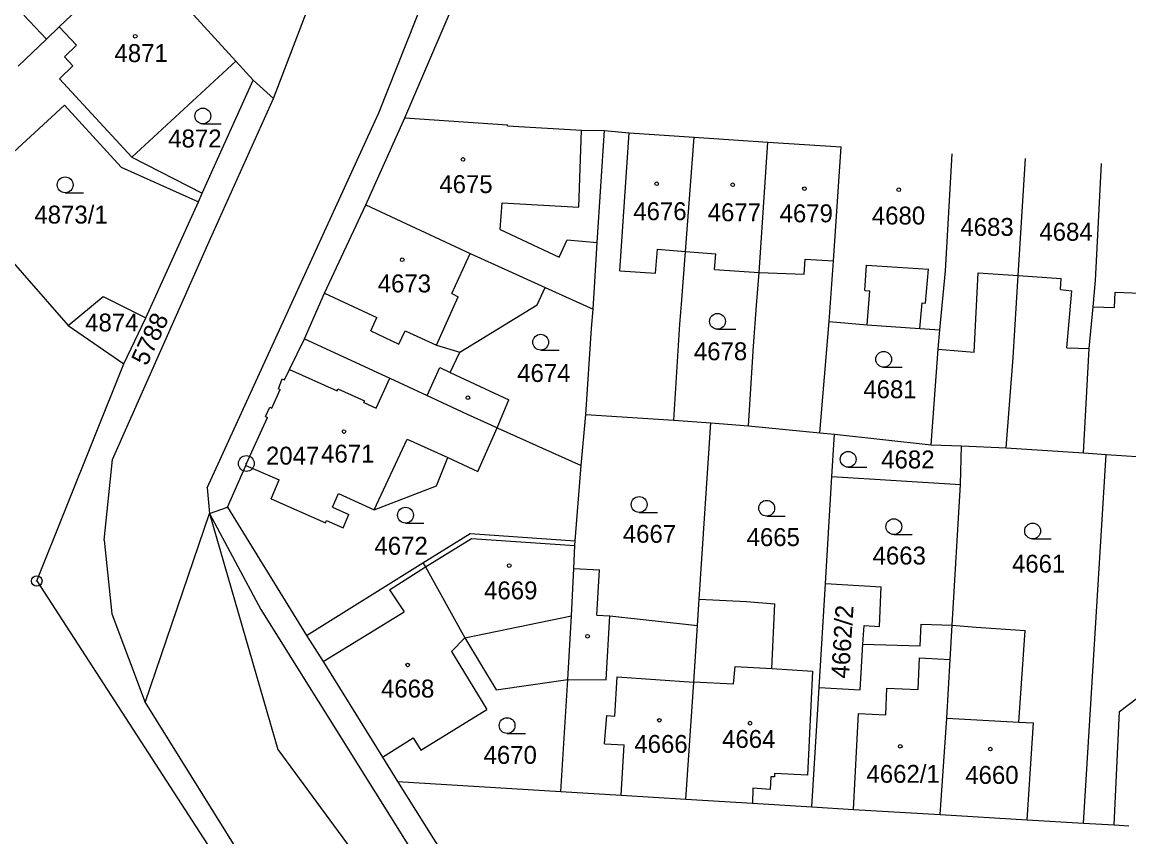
# Model space of a CAD drawing. Extents: x -735092 to -733385, y -1122435 to -1118992.
# Drawn here: x -734733.2 to -734628.2, y -1119440 to -1119362.8 of the extents above; entities that cross this region are included whole.
import ezdxf

# ---------------------------------------------------------------- set-up
doc = ezdxf.new("R2010")
doc.units = 0
for name, color, linetype in [('Vrstva 1', 7, 'Continuous'), ('Vrstva 17', 7, 'Continuous'), ('Vrstva 18', 7, 'Continuous'), ('Vrstva 19', 7, 'Continuous'), ('Vrstva 25', 7, 'Continuous'), ('Vrstva 4', 7, 'Continuous')]:
    doc.layers.add(name, color=color, linetype=linetype)

msp = doc.modelspace()

# ---------------------------------------------------------------- linework, layer by layer
at = {"layer": 'Vrstva 1'}
for points in [[(-734729.71, -1119363.21), (-734722.32, -1119356.18)], [(-734722.32, -1119356.18), (-734712.94, -1119366.45)], [(-734709.39, -1119370), (-734703.94, -1119355.73)], [(-734699.37, -1119371.37), (-734694.14, -1119358.12)], [(-734696.92, -1119371.82), (-734691.02, -1119358.02)], [(-734730.91, -1119364.36), (-734729.71, -1119363.21)], [(-734733.61, -1119366.92), (-734730.91, -1119364.36)], [(-734722.81, -1119375.57), (-734712.94, -1119366.45)], [(-734712.94, -1119366.45), (-734711.3, -1119368.27)], [(-734716.13, -1119378.97), (-734711.3, -1119368.27)], [(-734711.3, -1119368.27), (-734709.39, -1119370)], [(-734715.35, -1119383.29), (-734709.39, -1119370)], [(-734734.03, -1119375.09), (-734729.21, -1119370.63)], [(-734729.21, -1119370.63), (-734723.84, -1119376.52)], [(-734746.35, -1119371.53), (-734728.84, -1119391.54)], [(-734715.66, -1119406.92), (-734699.37, -1119371.37)], [(-734700.63, -1119380.07), (-734696.92, -1119371.82)], [(-734696.92, -1119371.82), (-734687.18, -1119372.48)], [(-734687.19, -1119372.6), (-734687.18, -1119372.48)], [(-734687.19, -1119372.6), (-734680.15, -1119372.99)], [(-734680.15, -1119372.99), (-734677.98, -1119373.03)], [(-734678.66, -1119383.67), (-734677.98, -1119373.03)], [(-734677.98, -1119373.03), (-734675.64, -1119373.26)], [(-734675.64, -1119373.26), (-734669.47, -1119373.67)], [(-734670.3, -1119384.52), (-734669.47, -1119373.67)], [(-734669.47, -1119373.67), (-734662.49, -1119374.13)], [(-734663.31, -1119386.51), (-734662.49, -1119374.13)], [(-734662.49, -1119374.13), (-734655.52, -1119374.58)], [(-734656.27, -1119385.39), (-734655.52, -1119374.58)], [(-734645.64, -1119386.33), (-734644.99, -1119375.26)], [(-734723.84, -1119376.52), (-734716.5, -1119379.79)], [(-734722.81, -1119375.57), (-734716.13, -1119378.97)], [(-734638.74, -1119386.8), (-734638.03, -1119375.7)], [(-734631.41, -1119387.27), (-734630.83, -1119376.15)], [(-734716.5, -1119379.79), (-734716.13, -1119378.97)], [(-734721.48, -1119390.8), (-734716.5, -1119379.79)], [(-734704.54, -1119388.46), (-734700.63, -1119380.07)], [(-734700.63, -1119380.07), (-734690.73, -1119384.71)], [(-734724.66, -1119404.24), (-734715.35, -1119383.29)], [(-734678.93, -1119387.92), (-734678.66, -1119383.67)], [(-734690.73, -1119384.71), (-734687.09, -1119386.36)], [(-734670.68, -1119389.51), (-734670.3, -1119384.52)], [(-734670.3, -1119384.52), (-734667.42, -1119384.72)], [(-734667.53, -1119386.21), (-734667.42, -1119384.72)], [(-734656.67, -1119391.16), (-734656.27, -1119385.39)], [(-734687.09, -1119386.36), (-734683.62, -1119387.93)], [(-734667.53, -1119386.21), (-734663.31, -1119386.51)], [(-734663.55, -1119389.63), (-734663.31, -1119386.51)], [(-734646.17, -1119391.94), (-734645.64, -1119386.33)], [(-734639.23, -1119394.58), (-734638.74, -1119386.8)], [(-734684.37, -1119389.57), (-734683.62, -1119387.93)], [(-734683.62, -1119387.93), (-734679.07, -1119389.99)], [(-734679.07, -1119389.99), (-734678.93, -1119387.92)], [(-734631.64, -1119389.75), (-734631.41, -1119387.27)], [(-734728.84, -1119391.54), (-734725.54, -1119388.79)], [(-734725.54, -1119388.79), (-734721.48, -1119390.8)], [(-734706.43, -1119392.79), (-734704.54, -1119388.46)], [(-734691.69, -1119394.05), (-734684.37, -1119389.57)], [(-734679.2, -1119391.82), (-734679.07, -1119389.99)], [(-734670.83, -1119391.4), (-734670.68, -1119389.51)], [(-734663.84, -1119393.5), (-734663.55, -1119389.63)], [(-734632, -1119393.73), (-734631.64, -1119389.75)], [(-734723.57, -1119395.17), (-734721.48, -1119390.8)], [(-734657.54, -1119401.71), (-734656.67, -1119391.16)], [(-734656.67, -1119391.16), (-734653.05, -1119391.48)], [(-734728.84, -1119391.54), (-734723.57, -1119395.17)], [(-734679.75, -1119399.99), (-734679.2, -1119391.82)], [(-734671.39, -1119400.51), (-734670.83, -1119391.4)], [(-734653.05, -1119391.48), (-734648.07, -1119391.81)], [(-734648.07, -1119391.81), (-734646.17, -1119391.94)], [(-734646.34, -1119393.78), (-734646.17, -1119391.94)], [(-734707.87, -1119395.71), (-734706.43, -1119392.79)], [(-734706.43, -1119392.79), (-734698.34, -1119396.53)], [(-734692.61, -1119395.98), (-734691.69, -1119394.05)], [(-734664.31, -1119401.05), (-734663.84, -1119393.5)], [(-734646.99, -1119402.84), (-734646.34, -1119393.78)], [(-734632.53, -1119403.62), (-734632, -1119393.73)], [(-734731.83, -1119415.77), (-734723.57, -1119395.17)], [(-734639.88, -1119403.13), (-734639.23, -1119394.58)], [(-734708.32, -1119396.7), (-734707.87, -1119395.71)], [(-734692.61, -1119395.98), (-734687.05, -1119398.59)], [(-734708.89, -1119397.55), (-734708.54, -1119396.6)], [(-734708.54, -1119396.6), (-734708.32, -1119396.7)], [(-734698.34, -1119396.53), (-734694.79, -1119398.18)], [(-734709.53, -1119399.36), (-734708.74, -1119397.62)], [(-734708.89, -1119397.55), (-734708.74, -1119397.62)], [(-734694.79, -1119398.18), (-734691, -1119399.93)], [(-734688.16, -1119401.23), (-734687.05, -1119398.59)], [(-734710.13, -1119400.17), (-734709.71, -1119399.27)], [(-734709.71, -1119399.27), (-734709.53, -1119399.36)], [(-734711.95, -1119404.63), (-734709.94, -1119400.26)], [(-734710.13, -1119400.17), (-734709.94, -1119400.26)], [(-734691, -1119399.93), (-734688.76, -1119400.96)], [(-734680.18, -1119404.8), (-734679.75, -1119399.99)], [(-734679.75, -1119399.99), (-734671.39, -1119400.51)], [(-734671.39, -1119400.51), (-734667.88, -1119400.78)], [(-734690.01, -1119405.37), (-734688.16, -1119401.23)], [(-734688.76, -1119400.96), (-734688.16, -1119401.23)], [(-734688.16, -1119401.23), (-734680.18, -1119404.8)], [(-734668.99, -1119417.49), (-734667.88, -1119400.78)], [(-734667.88, -1119400.78), (-734664.31, -1119401.05)], [(-734664.31, -1119401.05), (-734657.54, -1119401.71)], [(-734657.54, -1119401.71), (-734656.15, -1119401.85)], [(-734656.4, -1119405.85), (-734656.15, -1119401.85)], [(-734656.15, -1119401.85), (-734646.99, -1119402.84)], [(-734646.99, -1119402.84), (-734644.13, -1119402.95)], [(-734644.21, -1119406.61), (-734644.13, -1119402.95)], [(-734644.13, -1119402.95), (-734639.88, -1119403.13)], [(-734639.88, -1119403.13), (-734632.53, -1119403.62)], [(-734632.55, -1119438.75), (-734630.39, -1119403.76)], [(-734632.53, -1119403.62), (-734630.39, -1119403.76)], [(-734630.39, -1119403.76), (-734625.56, -1119404.09)], [(-734725.45, -1119411.91), (-734724.66, -1119404.24)], [(-734713.75, -1119408.78), (-734712, -1119404.8)], [(-734712, -1119404.8), (-734711.95, -1119404.63)], [(-734712, -1119404.8), (-734708.83, -1119406.19)], [(-734693.93, -1119406.74), (-734692.85, -1119404.07)], [(-734692.85, -1119404.07), (-734690.01, -1119405.37)], [(-734680.76, -1119411.95), (-734680.18, -1119404.8)], [(-734657.02, -1119416.02), (-734656.4, -1119405.85)], [(-734656.4, -1119405.85), (-734644.21, -1119406.61)], [(-734715.66, -1119406.92), (-734715.44, -1119409.38)], [(-734709.61, -1119407.97), (-734708.83, -1119406.19)], [(-734699.84, -1119409.03), (-734693.93, -1119406.74)], [(-734644.99, -1119419.96), (-734644.21, -1119406.61)], [(-734709.61, -1119407.97), (-734704.44, -1119410.24)], [(-734703.79, -1119408.76), (-734703.22, -1119407.47)], [(-734703.22, -1119407.47), (-734699.84, -1119409.03)], [(-734715.44, -1119409.38), (-734713.75, -1119408.78)], [(-734713.75, -1119408.78), (-734706.26, -1119420.95)], [(-734703.79, -1119408.76), (-734702.22, -1119409.45)], [(-734721.56, -1119427.31), (-734715.44, -1119409.38)], [(-734715.44, -1119409.38), (-734708.97, -1119431.75)], [(-734715.44, -1119409.38), (-734710.57, -1119418.49)], [(-734704.44, -1119410.24), (-734704.35, -1119410.03)], [(-734704.35, -1119410.03), (-734702.78, -1119410.72)], [(-734702.78, -1119410.72), (-734702.22, -1119409.45)], [(-734725.45, -1119411.91), (-734724.71, -1119418.88)], [(-734695.2, -1119414.06), (-734690.73, -1119411.27)], [(-734690.73, -1119411.27), (-734680.76, -1119411.95)], [(-734680.78, -1119412.4), (-734680.76, -1119411.95)], [(-734680.89, -1119414.58), (-734680.78, -1119412.4)], [(-734706.26, -1119420.95), (-734695.2, -1119414.06)], [(-734695.2, -1119414.06), (-734694.96, -1119414.44)], [(-734694.96, -1119414.44), (-734691.24, -1119421.16)], [(-734681.11, -1119419.07), (-734680.89, -1119414.58)], [(-734680.89, -1119414.58), (-734678.45, -1119414.7)], [(-734678.7, -1119419), (-734678.45, -1119414.7)], [(-734731.83, -1119415.77), (-734712.85, -1119445.08)], [(-734657.63, -1119425.87), (-734657.02, -1119416.02)], [(-734657.02, -1119416.02), (-734651.73, -1119416.34)], [(-734651.88, -1119420.09), (-734651.73, -1119416.34)], [(-734710.57, -1119418.49), (-734688.84, -1119453.28)], [(-734669.16, -1119419.99), (-734668.99, -1119417.49)], [(-734668.99, -1119417.49), (-734664.52, -1119417.73)], [(-734664.52, -1119417.73), (-734661.82, -1119417.94)], [(-734662.11, -1119424.09), (-734661.82, -1119417.94)], [(-734724.71, -1119418.88), (-734721.56, -1119427.31)], [(-734681.45, -1119425.11), (-734681.11, -1119419.07)], [(-734678.7, -1119419), (-734677.46, -1119419.07)], [(-734677.46, -1119419.07), (-734669.16, -1119419.99)], [(-734669.51, -1119425.37), (-734669.16, -1119419.99)], [(-734653.47, -1119421.75), (-734653.36, -1119420)], [(-734653.36, -1119420), (-734651.88, -1119420.09)], [(-734648.04, -1119421.92), (-734647.95, -1119419.88)], [(-734647.95, -1119419.88), (-734644.99, -1119419.96)], [(-734645.18, -1119423.23), (-734644.99, -1119419.96)], [(-734644.99, -1119419.96), (-734642.71, -1119420.15)], [(-734642.71, -1119420.15), (-734638.09, -1119420.46)], [(-734638.69, -1119429.16), (-734638.09, -1119420.46)], [(-734706.26, -1119420.95), (-734704.66, -1119423.41)], [(-734692.49, -1119422.46), (-734691.24, -1119421.16)], [(-734691.24, -1119421.16), (-734688.27, -1119426.1)], [(-734692.49, -1119422.46), (-734689.13, -1119427.95)], [(-734653.73, -1119426.11), (-734653.47, -1119421.75)], [(-734653.47, -1119421.75), (-734648.04, -1119421.92)], [(-734704.66, -1119423.41), (-734699.05, -1119432.48)], [(-734645.51, -1119428.79), (-734645.18, -1119423.23)], [(-734662.11, -1119424.09), (-734658.24, -1119424.33), (-734658.73, -1119434.2), (-734661.84, -1119434.03), (-734661.85, -1119434.35), (-734662.21, -1119434.34), (-734662.25, -1119435.54), (-734663.9, -1119435.42), (-734663.95, -1119436.86)], [(-734688.27, -1119426.1), (-734681.45, -1119425.11)], [(-734682.11, -1119435.75), (-734681.45, -1119425.11)], [(-734670.25, -1119436.46), (-734669.51, -1119425.37)], [(-734658.32, -1119437.21), (-734657.63, -1119425.87)], [(-734657.63, -1119425.87), (-734653.73, -1119426.11)], [(-734721.56, -1119427.31), (-734712.89, -1119441.23)], [(-734695.4, -1119431.82), (-734689.13, -1119427.95)], [(-734629.13, -1119428.14), (-734627.54, -1119426.96)], [(-734646.15, -1119437.93), (-734645.51, -1119428.79)], [(-734629.65, -1119438.92), (-734629.13, -1119428.14)], [(-734638.69, -1119429.16), (-734637.29, -1119429.24)], [(-734637.89, -1119438.42), (-734637.29, -1119429.24)], [(-734699.05, -1119432.48), (-734696.12, -1119430.66)], [(-734696.12, -1119430.66), (-734695.4, -1119431.82)], [(-734708.97, -1119431.75), (-734696.3, -1119449)], [(-734699.05, -1119432.48), (-734697.62, -1119434.8)], [(-734697.62, -1119434.8), (-734682.11, -1119435.75)], [(-734697.62, -1119434.8), (-734687.36, -1119451.1)], [(-734682.11, -1119435.75), (-734676.4, -1119436.1)], [(-734676.4, -1119436.1), (-734670.25, -1119436.46)], [(-734670.25, -1119436.46), (-734663.95, -1119436.86)], [(-734663.95, -1119436.86), (-734658.32, -1119437.21)], [(-734658.32, -1119437.21), (-734654.36, -1119437.44)], [(-734654.36, -1119437.44), (-734646.15, -1119437.93)], [(-734646.15, -1119437.93), (-734637.89, -1119438.42)], [(-734637.89, -1119438.42), (-734632.55, -1119438.75)], [(-734632.55, -1119438.75), (-734629.65, -1119438.92)], [(-734629.65, -1119438.92), (-734628.23, -1119439.01)]]:
    msp.add_lwpolyline(points, dxfattribs=at)
at = {"layer": 'Vrstva 25'}
for points in [[(-734716.08, -1119372.41), (-734714.33, -1119372.41)], [(-734729.14, -1119378.94), (-734727.39, -1119378.94)], [(-734667.26, -1119391.89), (-734665.51, -1119391.89)], [(-734684.03, -1119393.87), (-734682.28, -1119393.87)], [(-734651.5, -1119395.49), (-734649.75, -1119395.49)], [(-734654.86, -1119404.98), (-734653.11, -1119404.98)], [(-734674.69, -1119409.26), (-734672.94, -1119409.26)], [(-734662.59, -1119409.62), (-734660.84, -1119409.62)], [(-734696.86, -1119410.28), (-734695.11, -1119410.28)], [(-734650.54, -1119411.37), (-734648.79, -1119411.37)], [(-734637.37, -1119411.78), (-734635.62, -1119411.78)], [(-734687.22, -1119430.24), (-734685.47, -1119430.24)]]:
    msp.add_lwpolyline(points, dxfattribs=at)
for centre, radius in [((-734722.49, -1119364.09), 0.175), ((-734716.08, -1119371.66), 0.75), ((-734691.4, -1119375.77), 0.175), ((-734729.14, -1119378.19), 0.75), ((-734673.03, -1119378.08), 0.175), ((-734665.82, -1119378.18), 0.175), ((-734659.02, -1119378.55), 0.175), ((-734650.07, -1119378.65), 0.175), ((-734697.17, -1119385.3), 0.175), ((-734667.26, -1119391.14), 0.75), ((-734684.03, -1119393.12), 0.75), ((-734651.5, -1119394.74), 0.75), ((-734690.94, -1119398.38), 0.175), ((-734702.69, -1119401.6), 0.175), ((-734654.86, -1119404.23), 0.75), ((-734711.95, -1119404.63), 0.75), ((-734711.95, -1119404.63), 0.032), ((-734674.69, -1119408.51), 0.75), ((-734696.86, -1119409.53), 0.75), ((-734662.59, -1119408.87), 0.75), ((-734650.54, -1119410.62), 0.75), ((-734637.37, -1119411.03), 0.75), ((-734687.02, -1119414.31), 0.175), ((-734731.83, -1119415.77), 0.5), ((-734731.83, -1119415.77), 0.032), ((-734679.58, -1119421.01), 0.175), ((-734696.65, -1119423.74), 0.175), ((-734687.22, -1119429.49), 0.75), ((-734672.78, -1119428.99), 0.175), ((-734664.18, -1119429.26), 0.175), ((-734649.93, -1119431.46), 0.175), ((-734641.38, -1119431.72), 0.175)]:
    msp.add_circle(centre, radius, dxfattribs=at)
at = {"layer": 'Vrstva 4'}
for points in [[(-734733.06, -1119362.1), (-734730.91, -1119364.36)], [(-734729.71, -1119363.21), (-734728.06, -1119364.94)], [(-734729.21, -1119366.03), (-734728.06, -1119364.94)], [(-734729.21, -1119366.03), (-734728.4, -1119366.89)], [(-734729.66, -1119368.12), (-734728.4, -1119366.89)], [(-734729.66, -1119368.12), (-734722.81, -1119375.57)], [(-734680.4, -1119380.31), (-734680.15, -1119372.99)], [(-734676.52, -1119386.34), (-734675.64, -1119373.26)], [(-734687.88, -1119382.44), (-734687.7, -1119379.9)], [(-734687.7, -1119379.9), (-734680.4, -1119380.31)], [(-734687.88, -1119382.44), (-734682.27, -1119385.05)], [(-734682.27, -1119385.05), (-734681.51, -1119383.42)], [(-734681.51, -1119383.42), (-734678.66, -1119383.67)], [(-734692.47, -1119388.49), (-734690.73, -1119384.71)], [(-734673.15, -1119386.57), (-734672.96, -1119384.3)], [(-734672.96, -1119384.3), (-734670.3, -1119384.52)], [(-734659.04, -1119386.66), (-734658.93, -1119385.25)], [(-734658.93, -1119385.25), (-734656.27, -1119385.39)], [(-734653.3, -1119388.22), (-734653.13, -1119385.8)], [(-734653.13, -1119385.8), (-734647.25, -1119386.18)], [(-734676.52, -1119386.34), (-734673.15, -1119386.57)], [(-734663.31, -1119386.51), (-734659.04, -1119386.66)], [(-734647.54, -1119389.4), (-734647.25, -1119386.18)], [(-734642.9, -1119394.06), (-734642.53, -1119386.54)], [(-734642.53, -1119386.54), (-734638.74, -1119386.8)], [(-734638.74, -1119386.8), (-734634.65, -1119387.06)], [(-734634.74, -1119388.13), (-734634.65, -1119387.06)], [(-734704.54, -1119388.46), (-734699.56, -1119390.78)], [(-734693.92, -1119393.41), (-734691.85, -1119388.8)], [(-734692.47, -1119388.49), (-734691.85, -1119388.8)], [(-734653.3, -1119388.22), (-734652.82, -1119388.25)], [(-734653.05, -1119391.48), (-734652.82, -1119388.25)], [(-734634.74, -1119388.13), (-734633.65, -1119388.23)], [(-734634.11, -1119393.65), (-734633.65, -1119388.23)], [(-734629.6, -1119389.81), (-734629.55, -1119388.38)], [(-734629.55, -1119388.38), (-734627.1, -1119388.46)], [(-734648.07, -1119391.81), (-734647.85, -1119389.37)], [(-734647.85, -1119389.37), (-734647.54, -1119389.4)], [(-734631.64, -1119389.75), (-734629.6, -1119389.81)], [(-734700.15, -1119392.05), (-734699.56, -1119390.78)], [(-734700.15, -1119392.05), (-734697.49, -1119393.29)], [(-734697.49, -1119393.29), (-734696.88, -1119392.03)], [(-734696.88, -1119392.03), (-734693.92, -1119393.41)], [(-734693.92, -1119393.41), (-734691.69, -1119394.05)], [(-734646.34, -1119393.78), (-734642.9, -1119394.06)], [(-734634.11, -1119393.65), (-734632, -1119393.73)], [(-734707.87, -1119395.71), (-734703.34, -1119397.73)], [(-734694.79, -1119398.18), (-734693.6, -1119395.51)], [(-734693.6, -1119395.51), (-734692.61, -1119395.98)], [(-734703.34, -1119397.73), (-734703.26, -1119397.54)], [(-734703.26, -1119397.54), (-734700.74, -1119398.67)], [(-734699.65, -1119399.37), (-734698.34, -1119396.53)], [(-734700.82, -1119398.85), (-734700.74, -1119398.67)], [(-734700.82, -1119398.85), (-734699.65, -1119399.37)], [(-734699.84, -1119409.03), (-734696.69, -1119402.31)], [(-734696.69, -1119402.31), (-734692.85, -1119404.07)], [(-734694.96, -1119414.44), (-734690.61, -1119411.73)], [(-734690.61, -1119411.73), (-734680.78, -1119412.4)], [(-734698.37, -1119416.62), (-734694.96, -1119414.44)], [(-734698.37, -1119416.62), (-734696.98, -1119418.69)], [(-734704.66, -1119423.41), (-734696.98, -1119418.69)], [(-734691.24, -1119421.16), (-734681.11, -1119419.07)], [(-734677.81, -1119425.15), (-734677.46, -1119419.07)], [(-734648.22, -1119426.06), (-734648.09, -1119423.07)], [(-734648.09, -1119423.07), (-734645.18, -1119423.23)], [(-734665.73, -1119425.56), (-734665.58, -1119423.88), (-734662.11, -1119424.09)], [(-734681.45, -1119425.11), (-734677.81, -1119425.15)], [(-734676.99, -1119428.59), (-734676.77, -1119424.87)], [(-734676.77, -1119424.87), (-734669.51, -1119425.37)], [(-734665.73, -1119425.56), (-734669.51, -1119425.37)], [(-734651.28, -1119428.47), (-734651.19, -1119425.94)], [(-734651.19, -1119425.94), (-734648.22, -1119426.06)], [(-734677.98, -1119431.21), (-734677.77, -1119428.54)], [(-734677.77, -1119428.54), (-734676.99, -1119428.59)], [(-734654.36, -1119437.44), (-734653.88, -1119428.33)], [(-734653.88, -1119428.33), (-734651.28, -1119428.47)], [(-734645.51, -1119428.79), (-734638.69, -1119429.16)], [(-734677.98, -1119431.21), (-734676.11, -1119431.33)], [(-734676.4, -1119436.1), (-734676.11, -1119431.33)]]:
    msp.add_lwpolyline(points, dxfattribs=at)

# ---------------------------------------------------------------- texts
at = {"layer": 'Vrstva 17'}
msp.add_text('2047', height=1.7, dxfattribs=at).set_placement((-734710.09, -1119404.73))
at = {"layer": 'Vrstva 18'}
for s, p in [('4872', (-734719.36, -1119374.64)), ('4873/1', (-734732.058, -1119381.86)), ('4874', (-734727.24, -1119392.1)), ('4678', (-734669.5, -1119394.83)), ('4674', (-734686.26, -1119396.89)), ('4681', (-734653.43, -1119398.43)), ('4682', (-734651.73, -1119405.09)), ('4667', (-734676.24, -1119412.15)), ('4665', (-734664.5, -1119412.46)), ('4672', (-734699.8, -1119413.28)), ('4663', (-734652.55, -1119414.21)), ('4661', (-734639.33, -1119414.98)), ('4670', (-734689.45, -1119433.12))]:
    msp.add_text(s, height=1.7, dxfattribs=at).set_placement(p)
for s, rotation, p in [('5788', 65.10052, (-734721.397, -1119395.445)), ('4662/2', 86.30069, (-734654.796, -1119425.058))]:
    msp.add_text(s, height=1.7, rotation=rotation, dxfattribs=at).set_placement(p)
at = {"layer": 'Vrstva 19'}
for s, p in [('4871', (-734724.46, -1119366.54)), ('4675', (-734693.65, -1119378.97)), ('4676', (-734675.25, -1119381.54)), ('4677', (-734668.19, -1119381.64)), ('4679', (-734661.37, -1119381.74)), ('4680', (-734652.62, -1119381.95)), ('4683', (-734644.22, -1119383.03)), ('4684', (-734636.73, -1119383.49)), ('4673', (-734699.49, -1119388.39)), ('4671', (-734704.86, -1119404.54)), ('4669', (-734689.4, -1119417.51)), ('4668', (-734699.18, -1119426.83)), ('4664', (-734666.82, -1119431.61)), ('4666', (-734675.15, -1119432.08)), ('4662/1', (-734653.13, -1119434.92)), ('4660', (-734643.76, -1119435.02))]:
    msp.add_text(s, height=1.7, dxfattribs=at).set_placement(p)

doc.saveas('drawing.dxf')
